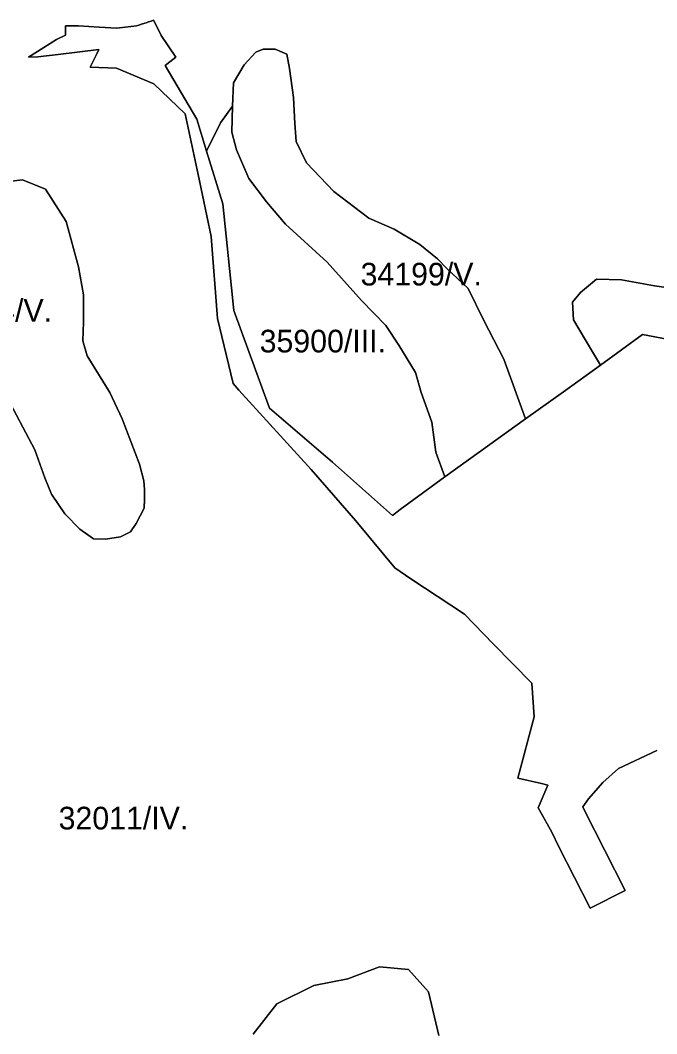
# Model space of a CAD drawing. Extents: x -521621 to -516761, y -1190184 to -1184927.
# Drawn here: x -520107 to -519686, y -1188092 to -1187422 of the extents above; entities that cross this region are included whole.
import ezdxf

# ---------------------------------------------------------------- set-up
doc = ezdxf.new("R2010")
doc.units = 0
doc.layers.add('BPEJ_s', color=7, linetype='Continuous')

msp = doc.modelspace()

# ---------------------------------------------------------------- linework, layer by layer
at = {"layer": 'BPEJ_s'}
for p, q in [((-520068.5, -1187425.26), (-520076.97, -1187425.26)), ((-520076.97, -1187425.26), (-520076.97, -1187431.47)), ((-520054.86, -1187426.09), (-520068.5, -1187425.26)), ((-520043.08, -1187426.71), (-520054.86, -1187426.09)), ((-520030.06, -1187425.26), (-520043.08, -1187426.71)), ((-520028.42, -1187424.72), (-520030.06, -1187425.26)), ((-520026.85, -1187424.2), (-520028.42, -1187424.72)), ((-520023.07, -1187422.95), (-520026.85, -1187424.2)), ((-520022.04, -1187422.61), (-520023.07, -1187422.95)), ((-520020.38, -1187422.06), (-520022.04, -1187422.61)), ((-520018.79, -1187421.54), (-520020.38, -1187422.06)), ((-520016.62, -1187425.68), (-520018.79, -1187421.54)), ((-520013.73, -1187431.67), (-520016.62, -1187425.68)), ((-520082.97, -1187434.36), (-520101.58, -1187446)), ((-520076.97, -1187431.47), (-520082.97, -1187434.36)), ((-520004.02, -1187445.95), (-520013.73, -1187431.67)), ((-520081.96, -1187444.27), (-520055.07, -1187440.98)), ((-520055.07, -1187440.98), (-520056.51, -1187444.08)), ((-519946.32, -1187440.67), (-519951.04, -1187442.61)), ((-519938.28, -1187440.67), (-519946.32, -1187440.67)), ((-519930.51, -1187444), (-519938.28, -1187440.67)), ((-520101.58, -1187446), (-520095.34, -1187445.82)), ((-520095.34, -1187445.82), (-520081.96, -1187444.27)), ((-520056.51, -1187444.08), (-520060.65, -1187452.57)), ((-520007.94, -1187449.05), (-520004.02, -1187445.95)), ((-519951.04, -1187442.61), (-519958.81, -1187450.94)), ((-519928.85, -1187453.44), (-519930.51, -1187444)), ((-520060.65, -1187452.57), (-520043.28, -1187453.19)), ((-520043.28, -1187453.19), (-520018.48, -1187463.53)), ((-520011.04, -1187451.53), (-520007.94, -1187449.05)), ((-519990.2, -1187487.01), (-520011.04, -1187451.53)), ((-519958.81, -1187450.94), (-519965.74, -1187462.87)), ((-519926.08, -1187472.59), (-519928.85, -1187453.44)), ((-520018.48, -1187463.53), (-519997.95, -1187483.56)), ((-519965.74, -1187462.87), (-519966.43, -1187478.47)), ((-519925.24, -1187489.8), (-519926.08, -1187472.59)), ((-519966.43, -1187478.47), (-519974.55, -1187489.31)), ((-519997.95, -1187483.56), (-519989.34, -1187523.63)), ((-519983.68, -1187508.23), (-519990.2, -1187487.01)), ((-519974.55, -1187489.31), (-519983.68, -1187508.23)), ((-519924.41, -1187501.73), (-519925.24, -1187489.8)), ((-519917.48, -1187515.89), (-519924.41, -1187501.73)), ((-519899.45, -1187534.76), (-519917.48, -1187515.89)), ((-520105.54, -1187527.18), (-520122.63, -1187529.08)), ((-520090.34, -1187533.35), (-520105.54, -1187527.18)), ((-519989.34, -1187523.63), (-519980.73, -1187564.56)), ((-520076.57, -1187554.73), (-520090.34, -1187533.35)), ((-519876.15, -1187552.52), (-519899.45, -1187534.76)), ((-520068.5, -1187584.66), (-520076.57, -1187554.73)), ((-519859.45, -1187559.82), (-519876.15, -1187552.52)), ((-519842.5, -1187569.89), (-519859.45, -1187559.82)), ((-519980.73, -1187564.56), (-519976.42, -1187618.85)), ((-519830.85, -1187579.42), (-519842.5, -1187569.89)), ((-519824.56, -1187585.83), (-519830.85, -1187579.42)), ((-520065.18, -1187603.19), (-520068.5, -1187584.66)), ((-519810.41, -1187599.15), (-519824.56, -1187585.83)), ((-519725.54, -1187592.77), (-519736.07, -1187601.65)), ((-519708.89, -1187593.32), (-519725.54, -1187592.77)), ((-519687.26, -1187597.21), (-519708.89, -1187593.32)), ((-519800.15, -1187620.24), (-519810.41, -1187599.15)), ((-519736.07, -1187601.65), (-519741.34, -1187608.03)), ((-519661.18, -1187601.09), (-519687.26, -1187597.21)), ((-520065.18, -1187621.25), (-520065.18, -1187603.19)), ((-519741.34, -1187608.03), (-519740.79, -1187619.69)), ((-520065.65, -1187633.6), (-520065.18, -1187621.25)), ((-519976.42, -1187618.85), (-519966.09, -1187661.93)), ((-519786.83, -1187645.78), (-519800.15, -1187620.24)), ((-519740.79, -1187619.69), (-519728.86, -1187639.95)), ((-520062.8, -1187643.57), (-520065.65, -1187633.6)), ((-519728.86, -1187639.95), (-519722.87, -1187649.69)), ((-520047.61, -1187667.8), (-520062.8, -1187643.57)), ((-519772.51, -1187685.38), (-519786.83, -1187645.78)), ((-519722.87, -1187649.69), (-519747.38, -1187667.46)), ((-519966.09, -1187661.93), (-519962.36, -1187666.24)), ((-520117.41, -1187667.8), (-520097.46, -1187705.81)), ((-520039.54, -1187685.38), (-520047.61, -1187667.8)), ((-519962.36, -1187666.24), (-519914.48, -1187718.92)), ((-519747.38, -1187667.46), (-519772.51, -1187685.38)), ((-520028.14, -1187715.31), (-520039.54, -1187685.38)), ((-520097.46, -1187705.81), (-520090.82, -1187724.34)), ((-520025.29, -1187726.24), (-520028.14, -1187715.31)), ((-519914.48, -1187718.92), (-519884.85, -1187752.71)), ((-520090.82, -1187724.34), (-520086.28, -1187735.18)), ((-520024.67, -1187732.15), (-520025.29, -1187726.24)), ((-520086.28, -1187735.18), (-520077.45, -1187748.21)), ((-520024.67, -1187738.44), (-520024.67, -1187732.15)), ((-520024.9, -1187744.48), (-520024.67, -1187738.44)), ((-520077.45, -1187748.21), (-520067.68, -1187758.21)), ((-520030.25, -1187754.49), (-520024.9, -1187744.48)), ((-520033.97, -1187760.07), (-520030.25, -1187754.49)), ((-519884.85, -1187752.71), (-519859.15, -1187783.88)), ((-520067.68, -1187758.21), (-520058.61, -1187764.72)), ((-520040.71, -1187763.33), (-520033.97, -1187760.07)), ((-520058.61, -1187764.72), (-520050.48, -1187764.96)), ((-520050.48, -1187764.96), (-520040.71, -1187763.33)), ((-519859.15, -1187783.88), (-519848.45, -1187791.27)), ((-519848.45, -1187791.27), (-519812.86, -1187814.51)), ((-519812.86, -1187814.51), (-519793.87, -1187834.17)), ((-519793.87, -1187834.17), (-519768.25, -1187860.13)), ((-519768.25, -1187860.13), (-519766.91, -1187882.58)), ((-519766.91, -1187882.58), (-519777.62, -1187923.04)), ((-519710.91, -1187916.7), (-519685.53, -1187904.73)), ((-519721.39, -1187926.04), (-519710.91, -1187916.7)), ((-519777.62, -1187923.04), (-519761.98, -1187926.53)), ((-519757.81, -1187927.71), (-519764.18, -1187942.61)), ((-519761.98, -1187926.53), (-519757.81, -1187927.71)), ((-519730.89, -1187936.69), (-519721.39, -1187926.04)), ((-519734.58, -1187942.03), (-519730.89, -1187936.69)), ((-519764.18, -1187942.61), (-519763.17, -1187944.17)), ((-519733.51, -1187944.38), (-519734.58, -1187942.03)), ((-519763.17, -1187944.17), (-519755.07, -1187958.91)), ((-519706.62, -1187997.35), (-519733.51, -1187944.38)), ((-519755.07, -1187958.91), (-519750.58, -1187968.52)), ((-519750.58, -1187968.52), (-519729.67, -1188009.1)), ((-519729.67, -1188009.1), (-519706.62, -1187997.35)), ((-519869.15, -1188047.97), (-519890.09, -1188055.83)), ((-519849.96, -1188049.72), (-519869.15, -1188047.97)), ((-519836.87, -1188064.56), (-519849.96, -1188049.72)), ((-519890.09, -1188055.83), (-519912.78, -1188060.2)), ((-519912.78, -1188060.2), (-519937.21, -1188072.42)), ((-519829.89, -1188093.37), (-519836.87, -1188064.56)), ((-519937.21, -1188072.42), (-519952.92, -1188092.5))]:
    msp.add_line(p, q, dxfattribs=at)
for points in [[(-519685.53, -1187904.73), (-519710.91, -1187916.7), (-519721.39, -1187926.04), (-519730.89, -1187936.69), (-519734.58, -1187942.03), (-519733.51, -1187944.38), (-519706.62, -1187997.35), (-519729.67, -1188009.1), (-519750.58, -1187968.52), (-519755.07, -1187958.91), (-519763.17, -1187944.17), (-519764.18, -1187942.61), (-519757.81, -1187927.71), (-519761.98, -1187926.53), (-519777.62, -1187923.04), (-519766.91, -1187882.58), (-519768.25, -1187860.13), (-519793.87, -1187834.17), (-519812.86, -1187814.51), (-519848.45, -1187791.27), (-519859.15, -1187783.88), (-519884.85, -1187752.71), (-519914.48, -1187718.92), (-519962.36, -1187666.24), (-519966.09, -1187661.93), (-519976.42, -1187618.85), (-519980.73, -1187564.56), (-519989.34, -1187523.63), (-519997.95, -1187483.56), (-520018.48, -1187463.53), (-520043.28, -1187453.19), (-520060.65, -1187452.57), (-520056.51, -1187444.08), (-520055.07, -1187440.98), (-520081.96, -1187444.27), (-520095.34, -1187445.82), (-520101.58, -1187446), (-520082.97, -1187434.36), (-520076.97, -1187431.47), (-520076.97, -1187425.26), (-520068.5, -1187425.26), (-520054.86, -1187426.09), (-520043.08, -1187426.71), (-520030.06, -1187425.26), (-520028.42, -1187424.72), (-520026.85, -1187424.2), (-520023.07, -1187422.95), (-520022.04, -1187422.61), (-520020.38, -1187422.06), (-520018.79, -1187421.54), (-520016.62, -1187425.68), (-520013.73, -1187431.67), (-520004.02, -1187445.95), (-520007.94, -1187449.05), (-520011.04, -1187451.53), (-519990.2, -1187487.01), (-519983.68, -1187508.23), (-519972.98, -1187543.02), (-519965.66, -1187613.68), (-519941.97, -1187678.27), (-519900.23, -1187714.04), (-519860.56, -1187749.15), (-519855.59, -1187745.21), (-519826, -1187723.77), (-519803.25, -1187707.28), (-519772.51, -1187685.38), (-519747.38, -1187667.46), (-519722.87, -1187649.69), (-519695.16, -1187629.58), (-519511.79, -1187664.33)], [(-520122.63, -1187529.08), (-520105.54, -1187527.18), (-520090.34, -1187533.35), (-520076.57, -1187554.73), (-520068.5, -1187584.66), (-520065.18, -1187603.19), (-520065.18, -1187621.25), (-520065.65, -1187633.6), (-520062.8, -1187643.57), (-520047.61, -1187667.8), (-520039.54, -1187685.38), (-520028.14, -1187715.31), (-520025.29, -1187726.24), (-520024.67, -1187732.15), (-520024.67, -1187738.44), (-520024.9, -1187744.48), (-520030.25, -1187754.49), (-520033.97, -1187760.07), (-520040.71, -1187763.33), (-520050.48, -1187764.96), (-520058.61, -1187764.72), (-520067.68, -1187758.21), (-520077.45, -1187748.21), (-520086.28, -1187735.18), (-520090.82, -1187724.34), (-520097.46, -1187705.81), (-520117.41, -1187667.8)], [(-519511.79, -1187664.33), (-519695.16, -1187629.58), (-519722.87, -1187649.69), (-519728.86, -1187639.95), (-519740.79, -1187619.69), (-519741.34, -1187608.03), (-519736.07, -1187601.65), (-519725.54, -1187592.77), (-519708.89, -1187593.32), (-519687.26, -1187597.21), (-519661.18, -1187601.09)], [(-519952.92, -1188092.5), (-519937.21, -1188072.42), (-519912.78, -1188060.2), (-519890.09, -1188055.83), (-519869.15, -1188047.97), (-519849.96, -1188049.72), (-519836.87, -1188064.56), (-519829.89, -1188093.37)]]:
    msp.add_lwpolyline(points, dxfattribs=at)
for points in [[(-519966.43, -1187478.47), (-519965.74, -1187462.87), (-519958.81, -1187450.94), (-519951.04, -1187442.61), (-519946.32, -1187440.67), (-519938.28, -1187440.67), (-519930.51, -1187444), (-519928.85, -1187453.44), (-519926.08, -1187472.59), (-519925.24, -1187489.8), (-519924.41, -1187501.73), (-519917.48, -1187515.89), (-519899.45, -1187534.76), (-519876.15, -1187552.52), (-519859.45, -1187559.82), (-519842.5, -1187569.89), (-519830.85, -1187579.42), (-519824.56, -1187585.83), (-519810.41, -1187599.15), (-519800.15, -1187620.24), (-519786.83, -1187645.78), (-519772.51, -1187685.38), (-519803.25, -1187707.28), (-519826, -1187723.77), (-519831.85, -1187707.43), (-519834.59, -1187687.4), (-519841.54, -1187667.79), (-519845.36, -1187654.66), (-519856.46, -1187636.62), (-519865.05, -1187623.57), (-519881.14, -1187606.92), (-519903.89, -1187581.66), (-519931.35, -1187556.41), (-519944.11, -1187541.7), (-519955.76, -1187526.16), (-519963.8, -1187507.28), (-519966.85, -1187495.62)], [(-519983.68, -1187508.23), (-519974.55, -1187489.31), (-519966.43, -1187478.47), (-519966.85, -1187495.62), (-519963.8, -1187507.28), (-519955.76, -1187526.16), (-519944.11, -1187541.7), (-519931.35, -1187556.41), (-519903.89, -1187581.66), (-519881.14, -1187606.92), (-519865.05, -1187623.57), (-519856.46, -1187636.62), (-519845.36, -1187654.66), (-519841.54, -1187667.79), (-519834.59, -1187687.4), (-519831.85, -1187707.43), (-519826, -1187723.77), (-519855.59, -1187745.21), (-519860.56, -1187749.15), (-519900.23, -1187714.04), (-519941.97, -1187678.27), (-519965.66, -1187613.68), (-519972.98, -1187543.02)]]:
    msp.add_lwpolyline(points, close=True, dxfattribs=at)

# ---------------------------------------------------------------- texts
for s, p in [('34199/V.', (-519881.73, -1187597.05)), ('32054/V.', (-520166.24, -1187621.08)), ('35900/III.', (-519948.54, -1187641.35)), ('32011/IV.', (-520081.64, -1187957.01))]:
    msp.add_text(s, height=15, dxfattribs=at).set_placement(p)

doc.saveas('drawing.dxf')
